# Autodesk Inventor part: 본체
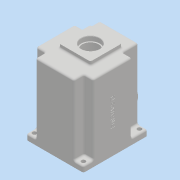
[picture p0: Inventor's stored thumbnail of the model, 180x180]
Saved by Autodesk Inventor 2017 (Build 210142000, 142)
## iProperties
Part Number: 본체
Material: 일반
Document SubType Name: Modeling
Designer: MRC
Density: 1 g/cm^3
Appearance: 기본값
Mass: 520.091 g
Surface Area: 1170.8 cm^2
Volume: 520.091 cm^3
Author: MRC
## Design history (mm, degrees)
sketch "스케치1"
  geometry: L1 (-49, 60)-(49, 60); L2 (49, 60)-(49, -50); L3 (49, -50)-(-49, -50); L4 (-49, -50)-(-49, 60); 2 further points
  constraints: 8 end point, 2 parallel, 1 horizontal, 1 midpoint, 1 perpendicular, 1 vertical alignment
  dimensions: "d0" = 98 distance of L1.start L1.end; "d45" = 50 distance from line of L3 point (0, 0); "d46" = 110 distance of L3.end L1.start
extrude "돌출1" new body sketch "스케치1" stored distance "d2" = 130; taper "d3" = 0 deg
sketch "스케치2"
  geometry: L1 (49, 60)-(-49, 60) reference; L2 (-49, 60)-(-49, -50) reference; L3 (49, -50)-(49, 60) reference; L4 (-49, -50)-(49, -50) reference; L5 (-33, 60)-(-33, 33); L6 (-33, 33)-(-49, 33); L7 (33, -33)-(49, -33); L8 (33, 33)-(49, 33); L9 (33, 33)-(33, 60); L10 (33, -33)-(33, -50); L11 (-49, -33)-(-33, -33); L12 (-33, -33)-(-33, -50); 1 further point
  constraints: 16 end point, 8 point on line, 3 equal length, 3 vertical, 2 horizontal, 2 perpendicular, 1 horizontal alignment
  dimensions: "d4" = 27 distance of L5.start L5.end; "d5" = 16 distance of L5.end L6.end; "d39" = 17 distance of L7.start L10.end; "d42" = 16 distance of L11.start L11.end; "d43" = 17 distance of L11.end L12.end
extrude "돌출2" cut sketch "스케치2" distance "d6" = 120; taper "d7" = 0 deg
sketch "스케치3"
  geometry: L1 (27, -16)-(-27, -16); L2 (-27, -16)-(-27, 38); L3 (-27, 38)-(27, 38); L4 (27, 38)-(27, -16); L5 (27, -16)-(-27, 38); L6 (-27, -16)-(27, 38); 7 further points; 1 other entity
  constraints: 12 end point, 3 midpoint, 2 parallel, 1 horizontal, 1 perpendicular, 1 vertical alignment, 1 other
  dimensions: "d9" = 61 dimension on point (0, 11); "d10" = 54 distance of L2.end L3.end; "d11" = 54 distance of L1.end L2.end
extrude "돌출3" join sketch "스케치3" distance "d12" = 7; taper "d13" = 0 deg
sketch "스케치4"
  geometry: L1 (0, 0)-(98, 0) reference; C1 r 22.5 at (49, -40); C2 r 15 at (49, -89); 1 further point
  constraints: 2 centre point, 2 vertical alignment
  dimensions: "d14" = 30 diameter of C2; "d15" = 45 diameter of C1; "d16" = 40 distance from line of L1 C1.centre; "d17" = 49 distance of C2.centre C1.centre
extrude "돌출4" join sketch "스케치4" distance "d18" = 5; taper "d19" = 0 deg
extrude "돌출5" join sketch "스케치4" distance "d20" = 10; taper "d21" = 0 deg
fillet "모깎기1" dims "d27" = 3
sketch "스케치7"
  geometry: L1 (-46, -50)-(46, -50) reference; L2 (-23, 50)-(-23, 35.143); L3 (23, 50)-(23, 35.143); L4 (23, 50)-(-23, 50); L5 (26, 36.729)-(26, 53); L6 (26, 53)-(-26, 53); L7 (-26, 53)-(-26, 36.729); A1 r 42 centre (0, 0) between (-23, 35.143) and (23, 35.143); A2 r 45 centre (0, 0) between (-26, 36.729) and (26, 36.729); 1 further point
  constraints: 12 end point, 4 point on circle, 2 centre point, 2 vertical, 1 coincident, 1 horizontal, 3 other
  dimensions: "d28" = 50 distance from line of L1 A1.centre; "d29" = 84 diameter of A1; "d30" = 46 distance of L3.start L2.start; "d31" = 50 distance from line of A1.centre L4; "d32" = 23 distance from line of L3 point (0, 0); "d33" = 3 radial gap between concentric circles of A1 A2
extrude "돌출7" cut sketch "스케치7" distance "d34" = 9; taper "d35" = 0 deg
sketch "스케치8"
  geometry: L1 (-26, 53)-(26, 53) reference; L2 (-26, 36.729)-(-26, 53) reference; L3 (26, 53)-(26, 36.729) reference; L4 (23, 50)-(-23, 50); L5 (-23, 50)-(-23, 35.143); L6 (23, 35.143)-(23, 50); A1 r 45 centre (0, 0) between (-26, 36.729) and (26, 36.729) reference; A2 r 42 centre (0, 0) between (-23, 35.143) and (23, 35.143); 1 further point
  constraints: 6 end point, 2 point on circle, 1 centre point, 3 other
  dimensions: "d36" = 3 distance between parallel lines of L1 L4
extrude "돌출8" cut sketch "스케치8" distance "d37" = 112; taper "d38" = 0 deg
sketch "스케치9"
  geometry: A1 r 21 centre (0, 11) between (8.978, -7.984) and (-8.978, -7.984); A2 r 15 centre (0, -20) between (-8.978, -7.984) and (8.978, -7.984); 1 further point
  constraints: 4 point on circle, 2 centre point, 2 vertical alignment
  dimensions: "d47" = 42 diameter of A1; "d48" = 30 diameter of A2; "d51" = 11 distance of A1.centre point (0, 0); "d52" = 20 distance of point (0, 0) A2.centre
fillet "모깎기3" dims "d49" = 6
fillet "모깎기4" dims "d50" = 3
extrude "돌출9" join sketch "스케치9" distance "d53" = 7; taper "d54" = 0 deg
sketch "스케치11"
  geometry: C1 r 11 at (0, -20); A1 r 15 centre (0, -20) between (-8.978, -7.984) and (8.978, -7.984) reference; 1 further point
  constraints: 1 centre point, 1 concentric
  dimensions: "d55" = 22 diameter of C1
extrude "돌출10" cut sketch "스케치11" distance "d56" = 7; taper "d57" = 0 deg
sketch "스케치12"
  geometry: C1 r 9.5 at (0, 0); C2 r 11 at (0, 0) reference; 1 further point
  constraints: 1 centre point, 1 concentric
  dimensions: "d58" = 19 diameter of C1
extrude "돌출11" cut sketch "스케치12" distance "d59" = 3; taper "d60" = 0 deg
sketch "스케치13"
  geometry: C1 r 17.5 at (0, 11); A1 r 21 centre (0, 11) between (8.978, -7.984) and (-8.978, -7.984) reference; 1 further point
  constraints: 1 centre point, 1 concentric
  dimensions: "d61" = 35 diameter of C1
extrude "돌출12" cut sketch "스케치13" distance "d62" = 10; taper "d63" = 0 deg
sketch "스케치16"
  geometry: C1 r 16 at (0, 11); 1 further point
  constraints: 1 centre point, 1 vertical alignment
  dimensions: "d65" = 32 diameter of C1; "d66" = 11 distance of point (0, 0) C1.centre
extrude "돌출13" cut sketch "스케치16" distance "d67" = 8.3; taper "d68" = 0 deg
sketch "스케치17"
  geometry: C1 r 14 at (0, 0); 1 further point
  constraints: 1 centre point, 1 vertical alignment
  dimensions: "d69" = 11 distance of point (0, -11) C1.centre; "d70" = 28 diameter of C1
extrude "돌출14" cut sketch "스케치17" stored distance "d71" = 8.3; taper "d72" = 0 deg
sketch "스케치18"
  geometry: C1 r 10 at (0, 0); C2 r 15 at (0, 0) reference; 1 further point
  constraints: 1 centre point, 1 concentric
  dimensions: "d73" = 20 diameter of C1
extrude "돌출15" cut sketch "스케치18" distance "d74" = 10; taper "d75" = 0 deg
sketch "스케치19"
  geometry: C1 r 15 at (0, 0); C2 r 10 at (0, 0) reference; 1 further point
  constraints: 1 centre point, 1 concentric
  dimensions: "d76" = 30 diameter of C1
extrude "돌출16" cut sketch "스케치19" distance "d77" = 5; taper "d78" = 0 deg
hole "구멍1" diameter "d81" = 33.376; stored, may be unused: countersink angle "d85" = 90 deg, drill point angle "d87" = 0 deg; dims "d79" = 10, "d80" = 10, "d82" = 70, "d83" = 4, "d84" = 2, "d86" = 77.3
sketch "스케치20"
  geometry: L1 (42, -43)-(-42, -43); L2 (-42, -43)-(-42, 53); L3 (-42, 53)-(42, 53); L4 (42, 53)-(42, -43); L5 (46, 60)-(-46, 60) reference; L6 (-49, 57)-(-49, -47) reference; L7 (-46, -50)-(46, -50) reference; C1 r 3.5 at (-42, 53); C2 r 3.5 at (42, 53); C3 r 3.5 at (42, -43); C4 r 3.5 at (-42, -43); 2 further points
  constraints: 8 end point, 4 centre point, 4 coincident, 2 parallel, 1 equal radius, 1 horizontal, 1 midpoint, 1 perpendicular, 1 vertical alignment
  dimensions: "d88" = 7 distance between parallel lines of L5 L3; "d89" = 7 distance between parallel lines of L6 L2; "d90" = 7 distance between parallel lines of L7 L1; "d91" = 7 diameter of C1; "d92" = 7 diameter of C2; "d93" = 7 diameter of C4
extrude "돌출17" cut sketch "스케치20" stored distance "d94" = 5; taper "d95" = 0 deg
sketch "스케치21"
  geometry: L1 (-36, 4)-(-41.809, 4); L2 (-36, -4)-(-41.809, -4); L3 (36, 4)-(41.809, 4); L4 (36, -4)-(41.809, -4); A1 r 4 centre (-36, 0) between (-36, -4) and (-36, 4); A2 r 4 centre (36, 0) between (36, 4) and (36, -4); A3 r 42 centre (0, 0) between (-25.375, 33.468) and (25.375, 33.468) reference; 1 further point
  constraints: 8 end point, 8 point on circle, 4 horizontal, 4 tangent, 2 centre point, 2 horizontal alignment, 1 equal radius
  dimensions: "d96" = 72 distance of A1.centre A2.centre; "d97" = 36 distance of point (0, 0) A2.centre; "d98" = 8 diameter of A1
extrude "돌출18" join sketch "스케치21" stored distance "d99" = 5; taper "d100" = 0 deg
hole "구멍2" diameter "d103" = 3.242; stored, may be unused: countersink angle "d107" = 90 deg, drill point angle "d109" = 118 deg; dims "d101" = 10, "d102" = 10, "d104" = 7, "d105" = 4, "d106" = 2, "d108" = 9
hole "구멍3" diameter "d112" = 3.242; stored, may be unused: countersink angle "d116" = 90 deg, drill point angle "d118" = 118 deg; dims "d110" = 10, "d111" = 10, "d113" = 7, "d114" = 4, "d115" = 2, "d117" = 9
fillet "모깎기5" dims "d119" = 3
fillet "모깎기6" dims "d120" = 3
fillet "모깎기7" dims "d121" = 3
fillet "모깎기8" dims "d122" = 3
fillet "모깎기9" dims "d123" = 3
fillet "모깎기10" dims "d124" = 0.3
fillet "모깎기11" dims "d125" = 0.3
chamfer "모따기1" distance "d126" = 0.8; stored, may be unused: second distance "d127" = 2, angle "d128" = 30 deg
fillet "모깎기12" dims "d129" = 3
fillet "모깎기13" dims "d130" = 3
fillet "모깎기14" dims "d131" = 3
fillet "모깎기15" dims "d132" = 3
fillet "모깎기16" dims "d133" = 3
fillet "모깎기17" dims "d134" = 3
fillet "모깎기18" dims "d135" = 3
sketch "스케치22"
  geometry: L1 (-130, 104)-(-130, 83) reference; L2 (-13, 80)-(-127, 80) reference; 2 further points
  constraints: 1 other
  dimensions: "d136" = 65 distance from line of L1 point (-65, 47); "d137" = 33 distance from line of point (-65, 47) L2
feature "엠보싱1" sketch "스케치22" dims "d4" = 27, "d5" = 16, "d39" = 17, "d138" = 0.5, "d139" = 0
chamfer "모따기2" distance "d140" = 1; stored, may be unused: second distance "d141" = 2, angle "d142" = 30 deg
chamfer "모따기3" distance "d143" = 1; stored, may be unused: second distance "d144" = 2, angle "d145" = 30 deg
node "솔리드1"
